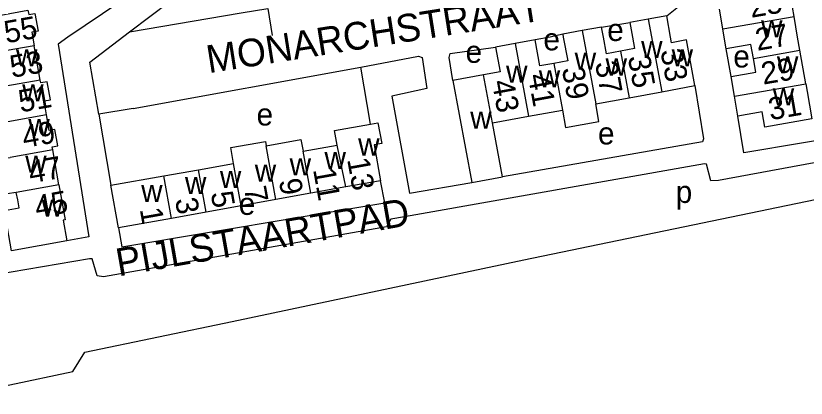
# Model space of a CAD drawing. Extents: x 162883 to 165538, y 383986 to 385172.
# Drawn here: x 164288.3 to 164430.6, y 384235 to 384303.8 of the extents above; entities that cross this region are included whole.
import ezdxf

# ---------------------------------------------------------------- set-up
doc = ezdxf.new("R2010")
doc.units = 0
for name, color, linetype in [('BLT_Basislijn', 7, 'Continuous'), ('BLT_Bebouwing', 7, 'Continuous'), ('BLT_Centroide', 7, 'Continuous'), ('BLT_Huisnummer', 7, 'Continuous'), ('BLT_Huisnummer_ tussenligend', 7, 'Continuous'), ('BLT_Onderverdeling_panden', 7, 'Continuous'), ('BLT_Straatnaam', 7, 'Continuous')]:
    doc.layers.add(name, color=color, linetype=linetype)

msp = doc.modelspace()

# ---------------------------------------------------------------- linework, layer by layer
at = {"layer": 'BLT_Basislijn'}
for p, q in [((164393.76, 384301.81), (164398.87, 384302.61)), ((164417.08, 384292.89), (164416.22, 384297.92)), ((164303.2, 384286.13), (164301.6, 384295.5)), ((164309.38, 384287.16), (164350.4, 384294.58)), ((164352.17, 384284.34), (164350.4, 384294.58)), ((164379.76, 384259.88), (164438.99, 384272.13)), ((164327.24, 384248.79), (164379.76, 384259.88))]:
    msp.add_line(p, q, dxfattribs=at)
for points in [[(164405.49, 384303.83), (164407.6, 384305.52), (164408.77, 384308.16), (164408.23, 384312.79), (164404.99, 384329.94), (164400.52, 384329.5), (164399.93, 384332.28), (164399.17, 384338.37), (164403.09, 384339.09), (164403.28, 384339.37), (164403.05, 384342.11), (164396.04, 384380.78), (164395.76, 384381.49), (164392.77, 384381.42), (164392.06, 384385.5)], [(164308.77, 384300.94), (164327.08, 384314.8)], [(164307.02, 384306.28), (164297.65, 384300), (164295.89, 384298.72), (164301.44, 384264.05), (164297.47, 384263.31)], [(164328.86, 384304.36), (164333.63, 384305.17), (164334.46, 384300.31)], [(164308.77, 384300.94), (164328.86, 384304.36)], [(164301.6, 384295.5), (164308.77, 384300.94)], [(164386.77, 384300.53), (164384.52, 384300), (164381.78, 384299.5)], [(164537.04, 384298.36), (164444.4, 384281.69), (164443.92, 384281.32), (164443.78, 384279.5), (164414.83, 384274.17), (164413.46, 384274.09), (164412.69, 384277.13), (164412.28, 384277.16), (164358.24, 384267.65), (164355.83, 384267.19), (164355.01, 384265.8), (164304.07, 384256.84), (164302.9, 384256.99), (164302.04, 384260.09), (164301.53, 384260.09), (164267.64, 384254.3)], [(164366.98, 384292.17), (164366.32, 384296.33), (164366.48, 384297.08), (164374.65, 384298.19)], [(164350.4, 384294.58), (164360.77, 384296.55), (164361.48, 384296.35), (164362.3, 384290.75), (164355.96, 384289.38), (164359.19, 384271.87), (164370.37, 384273.8)], [(164410.58, 384291.28), (164412.12, 384281.67), (164411.91, 384281.15), (164375.9, 384274.82)], [(164309.38, 384287.16), (164303.2, 384286.13)], [(164303.2, 384286.13), (164305.38, 384273.32)], [(164442.08, 384285.61), (164440.43, 384285.28), (164440.9, 384282.79), (164419.36, 384279.14), (164418.31, 384285.79)], [(164306.76, 384265.63), (164307.39, 384262.22), (164354.7, 384270.14), (164353.95, 384274.14)], [(164275.8, 384234.96), (164298.55, 384239.75), (164300.69, 384243.25), (164327.24, 384248.79)]]:
    msp.add_lwpolyline(points, dxfattribs=at)
at = {"layer": 'BLT_Bebouwing'}
for p, q in [((164428.43, 384303.69), (164427.37, 384309.81)), ((164405.49, 384303.83), (164402.18, 384303.22)), ((164415.61, 384301.47), (164414.99, 384305.04)), ((164402.18, 384303.22), (164398.87, 384302.61)), ((164390.27, 384301.17), (164386.77, 384300.53)), ((164393.76, 384301.81), (164390.27, 384301.17)), ((164381.78, 384299.5), (164378.21, 384298.84)), ((164292.68, 384292.27), (164291.59, 384298.45)), ((164378.21, 384298.84), (164374.65, 384298.19)), ((164430.53, 384291.56), (164429.48, 384297.63)), ((164372.51, 384293.19), (164366.98, 384292.17)), ((164417.7, 384289.34), (164417.08, 384292.89)), ((164366.98, 384292.17), (164370.37, 384273.8)), ((164404.59, 384290.17), (164410.58, 384291.28)), ((164398.72, 384289.09), (164404.59, 384290.17)), ((164392.7, 384287.98), (164398.72, 384289.09)), ((164418.31, 384285.79), (164417.7, 384289.34)), ((164380.63, 384285.75), (164386.7, 384286.87)), ((164374.1, 384284.55), (164380.63, 384285.75)), ((164375.9, 384274.82), (164374.1, 384284.55)), ((164296.02, 384273.4), (164294.91, 384279.69)), ((164340.04, 384279.45), (164346.15, 384280.52)), ((164321.19, 384276.12), (164327.47, 384277.23)), ((164314.91, 384275.01), (164321.19, 384276.12)), ((164353.95, 384274.14), (164347.68, 384273.01)), ((164370.37, 384273.8), (164375.9, 384274.82)), ((164347.68, 384273.01), (164341.4, 384271.87)), ((164341.4, 384271.87), (164335.12, 384270.74)), ((164328.85, 384269.61), (164322.57, 384268.48)), ((164335.12, 384270.74), (164328.85, 384269.61)), ((164322.57, 384268.48), (164316.29, 384267.35)), ((164297.47, 384263.31), (164287.5, 384261.53))]:
    msp.add_line(p, q, dxfattribs=at)
for points in [[(164270.2, 384298.36), (164279.16, 384299.94), (164278.66, 384302.78), (164285.54, 384303.97), (164290.46, 384304.84), (164290.6, 384304.05), (164291.7, 384304.25), (164292.27, 384301.07), (164291.16, 384300.88), (164291.59, 384298.45)], [(164410.58, 384291.28), (164409.07, 384299.49), (164406.38, 384299), (164406.2, 384300), (164405.49, 384303.83)], [(164398.87, 384302.61), (164399.34, 384300), (164399.7, 384297.95), (164397.17, 384297.49)], [(164429.48, 384297.63), (164429.06, 384300), (164428.43, 384303.69)], [(164397.17, 384297.49), (164394.64, 384297.02), (164394.09, 384300), (164393.76, 384301.81)], [(164416.22, 384297.92), (164415.86, 384300), (164415.61, 384301.47)], [(164385.15, 384295.28), (164382.64, 384294.82), (164381.78, 384299.5)], [(164386.77, 384300.53), (164386.87, 384300), (164387.66, 384295.74), (164385.15, 384295.28)], [(164374.65, 384298.19), (164375.47, 384293.74), (164372.51, 384293.19)], [(164421.1, 384296.18), (164420.66, 384298.69), (164416.22, 384297.92)], [(164417.08, 384292.89), (164421.54, 384293.66), (164421.1, 384296.18)], [(164293.8, 384285.98), (164293.35, 384288.51), (164294.52, 384288.72), (164293.94, 384291.95), (164292.78, 384291.74), (164292.68, 384292.27)], [(164430.53, 384291.56), (164430.77, 384290.18), (164431.62, 384285.26), (164423.18, 384283.79), (164422.7, 384286.55), (164418.31, 384285.79)], [(164386.7, 384286.87), (164387.26, 384283.71), (164393.28, 384284.82), (164392.7, 384287.98)], [(164294.91, 384279.69), (164294.81, 384280.23), (164295.82, 384280.41), (164295.29, 384283.34), (164294.3, 384283.16), (164293.8, 384285.98)], [(164346.15, 384280.52), (164345.67, 384283.17), (164352.17, 384284.34)], [(164352.17, 384284.34), (164353.49, 384284.58), (164354.17, 384280.83), (164352.79, 384280.58), (164353.95, 384274.14)], [(164327.47, 384277.23), (164326.98, 384280.1), (164333.21, 384281.22), (164333.36, 384280.42)], [(164333.36, 384280.42), (164339.59, 384281.55), (164340.04, 384279.45)], [(164288.36, 384272.04), (164285, 384271.51), (164283.89, 384277.81), (164287.25, 384278.33)], [(164305.38, 384273.32), (164314.91, 384275.01)], [(164296.02, 384273.4), (164297.14, 384267.1)], [(164306.76, 384265.63), (164305.38, 384273.32)], [(164287.5, 384261.53), (164286.22, 384268.78), (164288.86, 384269.24), (164288.61, 384270.67), (164288.36, 384272.04)], [(164297.14, 384267.1), (164296.81, 384267.05), (164297.47, 384263.31)], [(164316.29, 384267.35), (164306.76, 384265.63)]]:
    msp.add_lwpolyline(points, dxfattribs=at)
at = {"layer": 'BLT_Onderverdeling_panden'}
for p, q in [((164402.18, 384303.22), (164404.59, 384290.17)), ((164415.61, 384301.47), (164428.43, 384303.69)), ((164390.27, 384301.17), (164392.7, 384287.98)), ((164291.59, 384298.45), (164283.93, 384297.09)), ((164378.21, 384298.84), (164380.63, 384285.75)), ((164397.17, 384297.49), (164398.72, 384289.09)), ((164421.1, 384296.18), (164429.48, 384297.63)), ((164385.15, 384295.28), (164386.7, 384286.87)), ((164374.1, 384284.55), (164372.51, 384293.19)), ((164292.68, 384292.27), (164285.02, 384290.91)), ((164417.7, 384289.34), (164430.53, 384291.56)), ((164293.8, 384285.98), (164286.14, 384284.62)), ((164294.91, 384279.69), (164287.25, 384278.33)), ((164335.12, 384270.74), (164333.36, 384280.42)), ((164347.68, 384273.01), (164346.15, 384280.52)), ((164341.4, 384271.87), (164340.04, 384279.45)), ((164328.85, 384269.61), (164327.47, 384277.23)), ((164322.57, 384268.48), (164321.19, 384276.12)), ((164316.29, 384267.35), (164314.91, 384275.01)), ((164296.02, 384273.4), (164288.36, 384272.04))]:
    msp.add_line(p, q, dxfattribs=at)

# ---------------------------------------------------------------- texts
at = {"layer": 'BLT_Centroide'}
for s, p in [('e', (164394.78, 384299.3)), ('w', (164422.48, 384299.94)), ('e', (164383.29, 384297.62)), ('e', (164369.27, 384295.37)), ('w', (164400.88, 384296.23)), ('w', (164288.3, 384294.72)), ('w', (164388.92, 384294.11)), ('w', (164406.38, 384294.75)), ('e', (164417.49, 384294.53)), ('w', (164394.48, 384293.08)), ('w', (164425.34, 384293.47)), ('w', (164376.56, 384291.77)), ('w', (164382.45, 384290.95)), ('w', (164289.41, 384288.44)), ('w', (164424.59, 384287.69)), ('e', (164331.63, 384284.08)), ('w', (164290.52, 384282.16)), ('w', (164370.1, 384283.5)), ('e', (164393.12, 384280.67)), ('w', (164349.92, 384278.67)), ('w', (164289.96, 384275.59)), ('w', (164337.58, 384275.09)), ('w', (164343.86, 384276.22)), ('w', (164331.3, 384273.98)), ('w', (164325.02, 384272.84)), ('w', (164318.73, 384271.73)), ('w', (164310.84, 384270.31)), ('p', (164407.12, 384270.13)), ('e', (164328.42, 384267.98)), ('w', (164292.92, 384267.67))]:
    msp.add_text(s, height=4, dxfattribs=at).set_placement(p)
at = {"layer": 'BLT_Huisnummer'}
for s, rotation, p in [('25', 9.8404, (164420.71, 384303.47)), ('55', 10.0314, (164286.52, 384298.87)), ('33', 280.4453, (164404.35, 384297.55)), ('37', 280.4517, (164392.57, 384295.33)), ('43', 280.4442, (164373.98, 384291.99)), ('31', 9.8404, (164424.16, 384285.02)), ('49', 10.0314, (164289.77, 384280.01)), ('13', 280.2163, (164347.93, 384277.98)), ('9', 280.2163, (164335.63, 384274.2)), ('45', 10.0314, (164292.05, 384267.44)), ('5', 280.2163, (164323.35, 384271.92)), ('1', 280.2163, (164310.58, 384268.99))]:
    msp.add_text(s, height=4, rotation=rotation, dxfattribs=at).set_placement(p)
at = {"layer": 'BLT_Huisnummer_ tussenligend'}
for s, rotation, p in [('27', 9.8404, (164421.81, 384297.53)), ('53', 10.0314, (164287.56, 384292.66)), ('35', 280.4453, (164398.47, 384296.44)), ('29', 9.8404, (164422.87, 384291.43)), ('39', 280.4517, (164386.59, 384294.33)), ('41', 280.4517, (164380.46, 384293.1)), ('51', 10.0314, (164289.11, 384286.42)), ('47', 10.0314, (164290.92, 384273.65)), ('11', 280.2163, (164341.79, 384276.16)), ('7', 280.2163, (164329.34, 384272.82)), ('3', 280.2163, (164316.93, 384270.76))]:
    msp.add_text(s, height=4, rotation=rotation, dxfattribs=at).set_placement(p)
at = {"layer": 'BLT_Straatnaam'}
for s, height, rotation, p in [('MONARCHSTRAAT', 5, 8.989, (164323.01, 384293.49)), ('PIJLSTAARTPAD', 4.9999, 9.9788, (164306.77, 384256.89))]:
    msp.add_text(s, height=height, rotation=rotation, dxfattribs=at).set_placement(p)

doc.saveas('drawing.dxf')
